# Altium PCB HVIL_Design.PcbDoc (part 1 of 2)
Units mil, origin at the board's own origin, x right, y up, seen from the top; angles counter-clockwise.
Board outline 4950 x 3450 mil, 2 copper layers (Top Layer, Bottom Layer), stack 62 mil thick; 93 components, 48 nets, 203 pads, 53 vias.
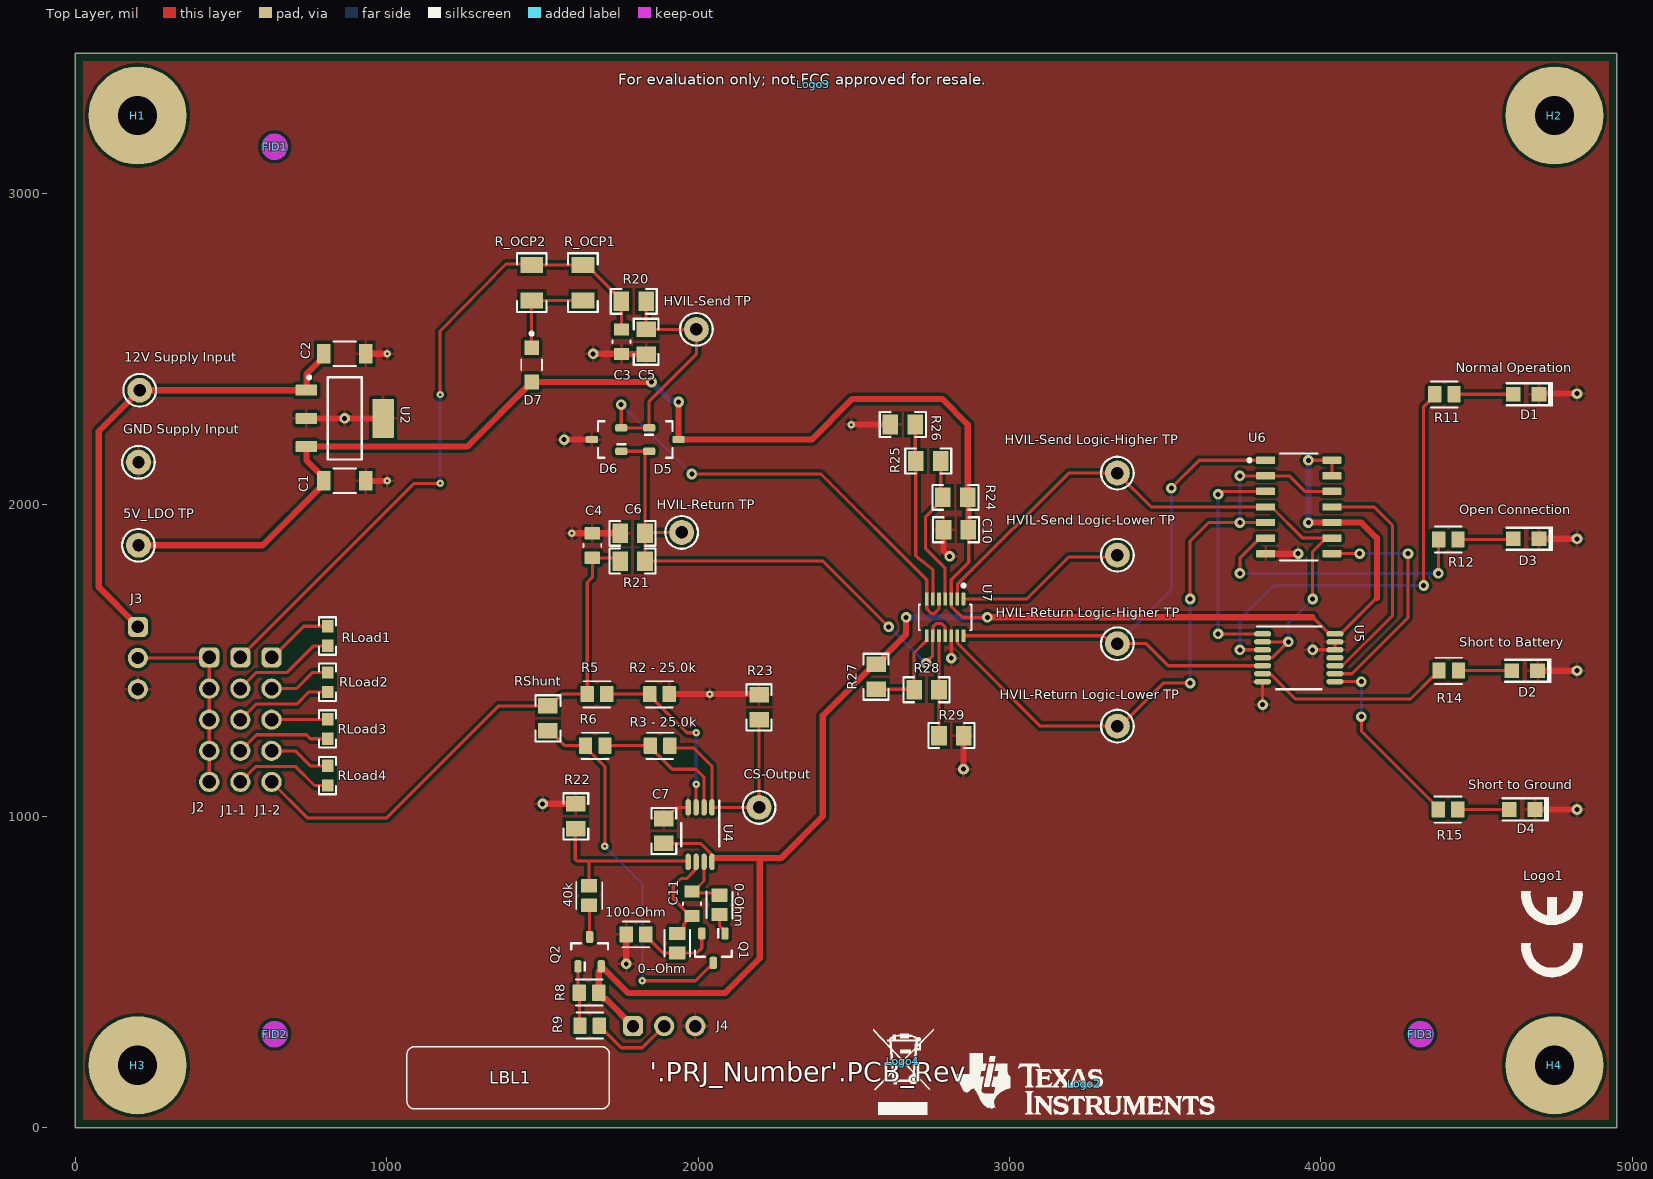
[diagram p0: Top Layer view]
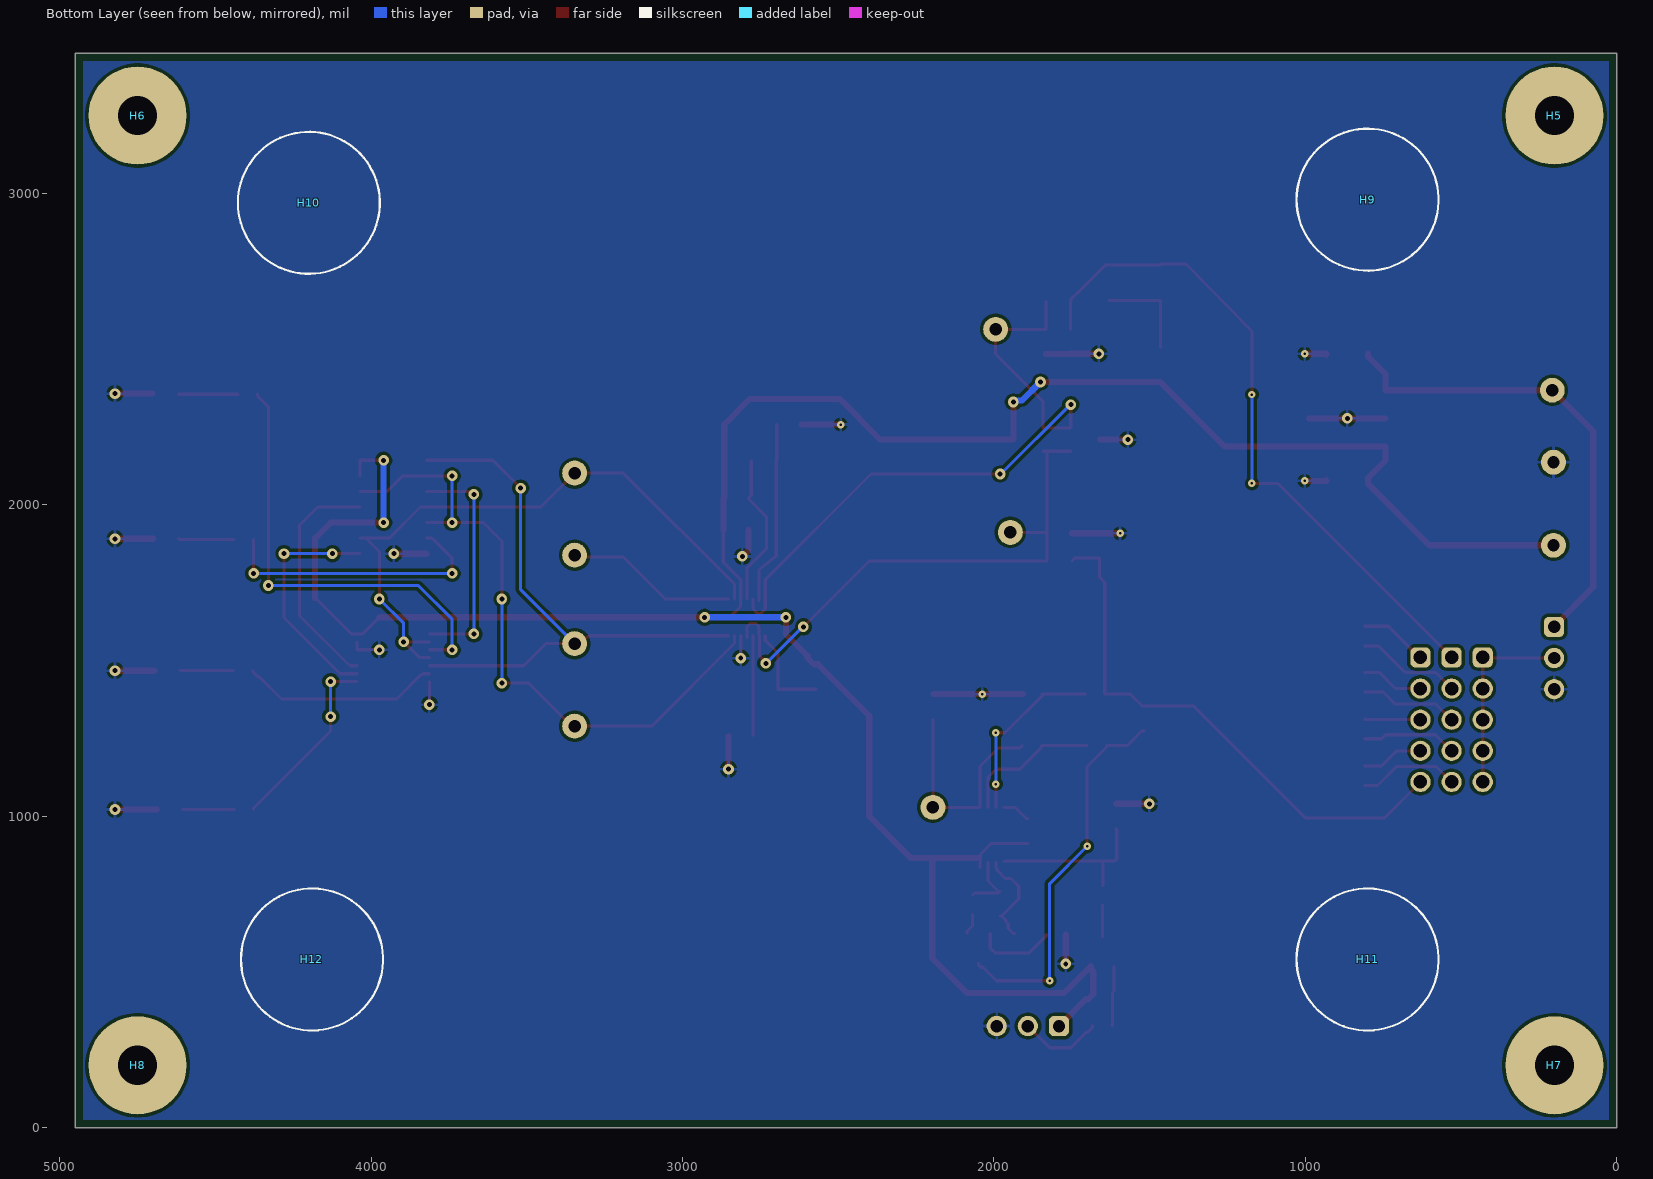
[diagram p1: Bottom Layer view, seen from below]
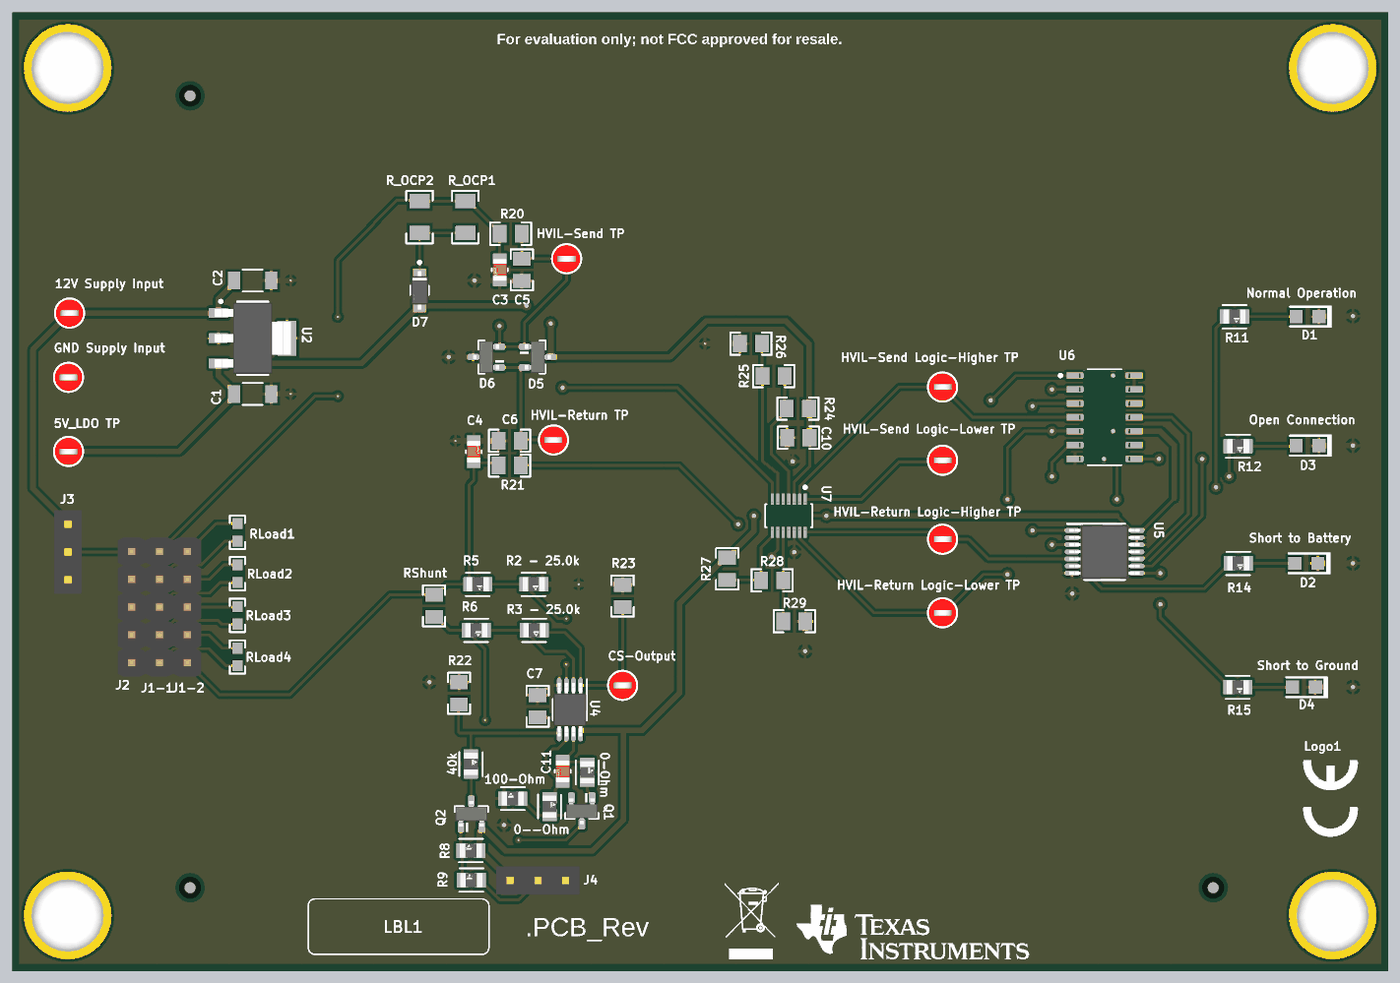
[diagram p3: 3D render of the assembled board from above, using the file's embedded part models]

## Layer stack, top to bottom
Top Solder: solder mask 0.4, Solder Resist, Dk 3.5
Top Layer: signal copper 1.4
Dielectric1: core 59.2, FR-4 High Tg, Dk 4.8
Bottom Layer: signal copper 1.4
Bottom Solder: solder mask 0.4, Solder Resist, Dk 3.5

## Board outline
0,0 4950,0 4950,3450 0,3450

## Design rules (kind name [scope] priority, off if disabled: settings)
AcuteAngle [All] p1: minimum=4.50000000000000E+0001 checktracksonly=FALSE
AssemblyTestPointUsage [All] p1: valid=2
BoardOutlineClearance BoardOutlineClearance_MountingHoles [OnCopper and InComponentClass('Mounting Holes')] p1: gap=39.37 ignorepadtopadclearanceinfootprint=FALSE
BoardOutlineClearance BoardOutlineClearance_Poly [OnCopper and IsPoly] p2: gap=25 ignorepadtopadclearanceinfootprint=FALSE
BoardOutlineClearance [OnCopper and Not InComponentClass('Logo') and not InComponentClass('FiducialMark') and not InRegion(1000,500,4000,800) and not InPoly] p3: gap=40 ignorepadtopadclearanceinfootprint=FALSE
Clearance Clearance_Keepouts [((IsTrack Or IsArc) And Not InPoly) And IsFree and IsKeepOut vs ((IsTrack Or IsArc) And Not InPoly) And IsFree and IsKeepOut] p1: gap=0 ignorepadtopadclearanceinfootprint=FALSE
Clearance Clearance_Poly [InPolygon] p2: gap=10 ignorepadtopadclearanceinfootprint=TRUE
Clearance Clearance_FiducialMark [IsKeepOut and InComponentClass('FiducialMark') vs IsPad and InComponentClass('FiducialMark')] p3: gap=0 ignorepadtopadclearanceinfootprint=FALSE
Clearance [All] p4: gap=7.87 ignorepadtopadclearanceinfootprint=TRUE
ComponentClearance ComponentClearance_MountingHoles_FiducialMarks [InComponentClass('Mounting Holes') vs InComponentClass('FiducialMark')] p1: gap=50 collisioncheckmode=3 verticalgap=10 showdistances=FALSE
ComponentClearance ComponentClearance_Shunt [InComponentClass('Header') vs InComponentClass('Shunt')] p2: gap=0 collisioncheckmode=3 verticalgap=0 showdistances=FALSE
ComponentClearance ComponentClearance_Logo [InComponentClass('Logo')] p3: gap=30 collisioncheckmode=3 verticalgap=10 showdistances=FALSE
ComponentClearance ComponentClearance_ScrewToNut [(HasFootprint('NY PMS 440 0025 PH')) vs (HasFootprint('Keystone_1902C'))] p4: gap=5 collisioncheckmode=3 verticalgap=10 showdistances=FALSE
ComponentClearance ComponentClearance_MountingHoles [InComponentClass('Mounting Holes')] p5: gap=100 collisioncheckmode=3 verticalgap=100000 showdistances=FALSE
ComponentClearance ComponentClearance_SmallPassives [HasFootprint('0201*') or HasFootprint('0402*') or HasFootprint('0508') or HasFootprint('0603*') or HasFootprint('0612') or HasFootprint('0805*') or HasFootprint('0815*') or HasFootprint('0830*') or HasFootprint('1206*') or HasFootprint('1210*') or HasFootprint('1808*') or HasFootprint('1812*') or HasFootprint('1825*') or HasFootprint('2010*') or HasFootprint('2220*') or HasFootprint('2225*') or HasFootprint('2512*') or HasFootprint('2728*') or HasFootprint('3518*') vs HasFootprint('0201*') or HasFootprint('0402*') or HasFootprint('0508') or HasFootprint('0603*') or HasFootprint('0612') or HasFootprint('0805*') or HasFootprint('0815*') or HasFootprint('0830*') or HasFootprint('1206*') or HasFootprint('1210*') or HasFootprint('1808*') or HasFootprint('1812*') or HasFootprint('1825*') or HasFootprint('2010*') or HasFootprint('2220*') or HasFootprint('2225*') or HasFootprint('2512*') or HasFootprint('2728*') or HasFootprint('3518*')] p6: gap=14.96 collisioncheckmode=3 verticalgap=10 showdistances=FALSE
ComponentClearance ComponentClearance_THtoSMT [IsThruComponent vs IsSMTComponent] p7: gap=30 collisioncheckmode=3 verticalgap=30 showdistances=FALSE
ComponentClearance ComponentClearance_THtoTH [IsThruComponent vs IsThruComponent] p8: gap=20 collisioncheckmode=3 verticalgap=30 showdistances=FALSE
ComponentClearance [All] p9: gap=20 collisioncheckmode=3 verticalgap=10 showdistances=FALSE
DiffPairsRouting [All] p1: maxlimit=100 minlimit=10 mostfreqgap=10 toplayer_minwidth=15 toplayer_maxwidth=15 toplayer_prefwidth=15 bottomlayer_minwidth=15 bottomlayer_maxwidth=15 bottomlayer_prefwidth=15 maxuncoupledlength=1000
FabricationTestPointUsage TestPointUsage [All] p1: valid=2 allowmultiple=FALSE
FabricationTestpoint Testpoint [All] p1: side=3 testpointundercomponent=TRUE minsize=40 maxsize=100 preferedsize=60 minholesize=0 maxholesize=40 preferedholesize=32 testpointgrid=1 allowsidetop=TRUE allowsidebottom=TRUE usegrid=TRUE gridtolerance=0.01
FanoutControl Fanout_LCC [IsLCC] p1: bgadir=Out bgaviamode=Centered fanoutstyle=Auto fanoutdirection=Alternating viagrid=1 // Fanout_LCC (Default Rule)
FanoutControl Fanout_BGA [IsBGA] p2: bgadir=Out bgaviamode=Centered fanoutstyle=Auto fanoutdirection=Alternating viagrid=1 // Fanout_BGA (Default Rule)
FanoutControl Fanout_Default [All] p4: bgadir=Out bgaviamode=Centered fanoutstyle=Auto fanoutdirection=Alternating viagrid=1 // Fanout_Default (Default Rule)
FanoutControl Fanout_Small [(CompPinCount < 5)] p5: bgadir=Out bgaviamode=Centered fanoutstyle=Auto fanoutdirection=OutThenIn viagrid=1 // Fanout_Small (Default Rule)
HoleSize [All] p1: absolutevalues=TRUE maxlimit=251 minlimit=7.87 maxpercent=80.000 minpercent=20.000
MinimumAnnularRing MinimumAnnularRing_ThermalPadVias [IsVia and InAnyComponent] p1: minimumring=5.91
MinimumAnnularRing [All] p2: minimumring=7.87
MinimumSolderMaskSliver MinimumSolderMaskSliver_Logo [InComponentClass('Logo') vs InComponentClass('Logo')] p1: minsoldermaskwidth=0.7
MinimumSolderMaskSliver [All] p2: minsoldermaskwidth=3.94
PlaneConnect [All] p1: planeconnectstyle=Relief reliefexpansion=10 reliefentries=4 reliefconductorwidth=10 reliefairgap=10
PolygonConnect [All] p1: connectstyle=Relief reliefconductorwidth=10 reliefentries=4 polygonreliefangle="90 Angle" airgapwidth=10
RoutingVias ThermalPadVias [IsVia and InAnyComponent] p1: holewidth=7.87 width=19.68 viastyle="Through Hole" minholewidth=7.87 minwidth=19.68 maxholewidth=12.99 maxwidth=23.62
RoutingVias [All] p2: holewidth=16 width=34 viastyle="Through Hole" minholewidth=7.87 minwidth=24 maxholewidth=40 maxwidth=65
SilkToBoardRegionClearance [Not ((IsComment or IsDesignator) And (Hide <> 'False')) and not InRegion(1000,500,4000,800)] p1:
SilkToSilkClearance SilkToSilkClearance_Pb-FreeLogo [(HasFootprint('Pb-Free_Overlay_Medium') OR HasFootprint('Pb-Free_Overlay_Small')) vs (HasFootprint('Pb-Free_Overlay_Medium') OR HasFootprint('Pb-Free_Overlay_Small'))] p1: silktosilkclearance=0
SilkToSilkClearance [All] p2: silktosilkclearance=3.94
SilkToSolderMaskClearance SilkToComponentPadClearance [(IsPad or IsFill or IsRegion) and InAnycomponent] p1: minsilkscreentomaskgap=5 clearancetoexposedcopper=TRUE
SilkToSolderMaskClearance "Silk to Solder Mask Opening" [All] p2: minsilkscreentomaskgap=3.94 clearancetoexposedcopper=FALSE
SolderMaskExpansion [All] p1: expansion=1.97 istentingtop=FALSE
UnRoutedNet [All] p1: checkbadconnections=TRUE
Width [All] p1: maxlimit=100 minlimit=6 preferedwidth=10 checkconnectedcopper=TRUE
14 further rules are at their usual default settings.

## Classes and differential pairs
component class HVIL_Design_BlankSheet: 0--Ohm 0-Ohm "5V_LDO TP" "12V Supply Input" 40k 100-Ohm C1 C2 C3 C4 C5 C6 C7 C10 C11 CS-Output D1 D2 D3 D4 D5 D6 D7 "GND Supply Input" "HVIL-Return Logic-Higher TP" "HVIL-Return Logic-Lower TP" "HVIL-Return TP" "HVIL-Send Logic-Higher TP" "HVIL-Send Logic-Lower TP" "HVIL-Send TP" J1-1 J1-2 J2 J3 J4 Q1 Q2 "R2 - 25.0k" "R3 - 25.0k" R5 R6 R8 R9 R11 R12 R14 R15 R20 R21 R22 R23 R24 R25 R26 R27 R28 R29 R_OCP1 R_OCP2 RLoad1 RLoad2 RLoad3 RLoad4 RShunt U2 U4 U5 U6 U7
component class Header: J1-1 J1-2 J2 J3 J4
component class Label: LBL1
component class AssemblyNote: ZZ1 ZZ2 ZZ3 ZZ4
component class FiducialMark: FID1 FID2 FID3
component class HVIL_Design_Hardware: FID1 FID2 FID3 H1 H2 H3 H4 H5 H6 H7 H8 H9 H10 H11 H12 LBL1 Logo1 Logo2 Logo3 Logo4 ZZ1 ZZ2 ZZ3 ZZ4
component class Logo: Logo2
component class "Mounting Holes": H1 H2 H3 H4

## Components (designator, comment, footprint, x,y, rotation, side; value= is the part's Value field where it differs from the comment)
0--Ohm "PCAN0805E1000BST5" FP-PCAN0805E1000BST5_0805-MFG 1932.95,592.26 r90 top value=100
0-Ohm "PCAN0805E1000BST5" FP-PCAN0805E1000BST5_0805-MFG 2068.86,715.25 r90 top value=100
"5V_LDO TP" "5000" Keystone5000 202.76,1870.08 r90 top
"12V Supply Input" "5000" Keystone5000 206.69,2368.11 r90 top
40k "PCAN0805E1001BST5" FP-PCAN0805E1001BST5_0805-MFG 1649.83,745.25 r90 top
100-Ohm "PCAN0805E1000BST5" FP-PCAN0805E1000BST5_0805-MFG 1800.52,620.53 r180 top value=100
C1 "CL31B106KBHNNNE" 1206_180 865.16,2076.77 r180 top value=10uF
C2 "CL31B106KBHNNNE" 1206_180 865.16,2485.06 r180 top value=10uF
C3 "08055F103K4T2A" FP-08055F103K4T2A_0805-MFG 1753.94,2523.62 r270 top
C4 "08055F103K4T2A" FP-08055F103K4T2A_0805-MFG 1660.43,1869.09 r90 top
C5 "GCM21BR71H104KA37K" 0805_HV 1833.31,2523.62 r90 top value=0.1uF
C6 "GCM21BR71H104KA37K" 0805_HV 1789.37,1908.39 r0 top value=0.1uF
C7 "GCM21BR71H104KA37K" 0805_HV 1890,952.72 r90 top value=0.1uF
C10 "GCM21BR71H104KA37K" 0805_HV 2828.03,1920 r180 top value=0.1uF
C11 "08055F103K4T2A" FP-08055F103K4T2A_0805-MFG 1980.28,718.88 r270 top
CS-Output "5000" Keystone5000 2195.87,1028.36 r90 top
D1 "LTST-C170KGKT" LTST-C170KGKT_Green 4659.45,2355.31 r0 top value=Green
D2 "LTST-C170KRKT" LED_LTST-C170_Red 4654.73,1467.52 r0 top value=Red
D3 "LTST-C170KSKT" LED_LTST-C170 4659.45,1891.05 r0 top value=Yellow
D4 "LTST-C170KRKT" LED_LTST-C170_Red 4646.38,1021.65 r0 top value=Red
D5 "BAT54C-7-F" SOT-23 1890.16,2209.66 r0 top value=30V
D6 "BAT54A-7-F" SOT-23 1706.06,2209.66 r180 top value=30V
D7 "PMEG4010EH,115" FP-PMEG4010EH_115_SOD123F-MFG 1465.55,2449.62 r270 top
FID1 "Fiducial" Fiducial10-20 640,3150 r0 top
FID2 "Fiducial" Fiducial10-20 640,300 r0 top
FID3 "Fiducial" Fiducial10-20 4320,300 r0 top
"GND Supply Input" "5000" Keystone5000 202.76,2136.81 r90 top
H1 "NY PMS 440 0025 PH" "NY PMS 440 0025 PH" 200,3250 r0 top locked
H2 "NY PMS 440 0025 PH" "NY PMS 440 0025 PH" 4750,3250 r0 top locked
H3 "NY PMS 440 0025 PH" "NY PMS 440 0025 PH" 200,200 r0 top locked
H4 "NY PMS 440 0025 PH" "NY PMS 440 0025 PH" 4750,200 r0 top locked
H5 "1902C" Keystone_1902C 200,3250 r180 bottom locked
H6 "1902C" Keystone_1902C 4750,3250 r180 bottom locked
H7 "1902C" Keystone_1902C 200,200 r180 bottom locked
H8 "1902C" Keystone_1902C 4750,200 r180 bottom locked
H9 "SJ-5303 (CLEAR)" Bumpon_SJ5003Transparent 800,2980 r180 bottom
H10 "SJ-5303 (CLEAR)" Bumpon_SJ5003Transparent 4200,2970 r180 bottom
H11 "SJ-5303 (CLEAR)" Bumpon_SJ5003Transparent 800,540 r180 bottom
H12 "SJ-5303 (CLEAR)" Bumpon_SJ5003Transparent 4190,540 r180 bottom
"HVIL-Return Logic-Higher TP" "5000" Keystone5000 3346.46,1554.13 r90 top
"HVIL-Return Logic-Lower TP" "5000" Keystone5000 3346.46,1289.37 r90 top
"HVIL-Return TP" "5000" Keystone5000 1947.12,1911.42 r90 top
"HVIL-Send Logic-Higher TP" "5000" Keystone5000 3346.46,2101.97 r90 top
"HVIL-Send Logic-Lower TP" "5000" Keystone5000 3346.46,1838.4 r90 top
"HVIL-Send TP" "5000" Keystone5000 1994.43,2563.62 r90 top
J1-1 "61300511121" Wurth_61300511121 530,1310 r270 top
J1-2 "61300511121" Wurth_61300511121 630,1310 r270 top
J2 "61300511121" Wurth_61300511121 430,1310 r270 top
J3 "TSW-103-07-G-S" TSW-103-07-G-S 200.79,1508.06 r270 top
J4 "TSW-103-07-G-S" TSW-103-07-G-S 1890.98,326.18 r0 top
LBL1 "THT-14-423-10" Label_650x200 1390,160 r0 top
Logo1 "CE Mark" CE_Mark_5mm 4742.13,621.06 r90 top
Logo2 "Texas Instruments" TI_Stacked_Overlay_Small 3240,140 r0 top
Logo3 "FCC disclaimer" FCC_disclaimer 2370,3350 r0 top
Logo4 "WEEE logo" WEEE_Minimum 2657.48,213.79 r0 top
Q1 "MMBTA05LT1G" SOT-23 2049.18,576.27 r270 top value="60 V"
Q2 "BC807-40LT1G" SOT-23 1651.57,565.09 r90 top value="45 V"
"R2 - 25.0k" "PCAN0805E1001BST5" FP-PCAN0805E1001BST5_0805-MFG 1875.98,1392.13 r0 top
"R3 - 25.0k" "PCAN0805E1001BST5" FP-PCAN0805E1001BST5_0805-MFG 1877.95,1226.55 r0 top
R5 "PCAN0805E1001BST5" FP-PCAN0805E1001BST5_0805-MFG 1675.2,1392.13 r0 top
R6 "PCAN0805E1001BST5" FP-PCAN0805E1001BST5_0805-MFG 1669.7,1226.55 r0 top
R8 "PCAN0805E1001BST5" FP-PCAN0805E1001BST5_0805-MFG 1649.83,433.2 r180 top
R9 "PCAN0805E1001BST5" FP-PCAN0805E1001BST5_0805-MFG 1651.57,327.13 r180 top
R11 "PCAN0805E1001BST5" FP-PCAN0805E1001BST5_0805-MFG 4396.79,2355.31 r0 top
R12 "PCAN0805E1001BST5" FP-PCAN0805E1001BST5_0805-MFG 4409.56,1889.09 r0 top
R14 "PCAN0805E1001BST5" FP-PCAN0805E1001BST5_0805-MFG 4410.43,1467.52 r0 top
R15 "PCAN0805E1001BST5" FP-PCAN0805E1001BST5_0805-MFG 4408.54,1021.65 r0 top
R20 "MCU0805MD1002BP100" 0805_HV 1793.31,2653.54 r0 top value=10.0k
R21 "MCU0805MD1002BP100" 0805_HV 1789.37,1819.43 r0 top value=10.0k
R22 "MCU0805MD1002BP100" 0805_HV 1607.29,999.72 r90 top value=10.0k
R23 "MCU0805MD1002BP100" 0805_HV 2195.87,1349.65 r90 top value=10.0k
R24 "MCU0805MD1002BP100" 0805_HV 2826.32,2024.2 r180 top value=10.0k
R25 "MCU0805MD1002BP100" 0805_HV 2739.17,2140.76 r180 top value=10.0k
R26 "MCU0805MD1002BP100" 0805_HV 2657.48,2257.87 r180 top value=10.0k
R27 "MCU0805MD1002BP100" 0805_HV 2571.65,1447.78 r270 top value=10.0k
R28 "MCU0805MD1002BP100" 0805_HV 2733.62,1406.14 r0 top value=10.0k
R29 "MCU0805MD1002BP100" 0805_HV 2813.62,1258.91 r0 top value=10.0k
R_OCP1 "CRCW1206220RJNEA" 1206 1630.31,2713.58 r90 top value=220
R_OCP2 "CRCW1206220RJNEA" 1206 1465.55,2713.58 r90 top value=220
RLoad1 "FC0603E50R0BTBST1" 0603 810.04,1578.74 r270 top value=50
RLoad2 "FC0603E50R0BTBST1" 0603 810.04,1430.32 r270 top value=50
RLoad3 "FC0603E50R0BTBST1" 0603 810.04,1280.31 r270 top value=50
RLoad4 "FC0603E50R0BTBST1" 0603 810.04,1130.32 r270 top value=50
RShunt "PATT0805E10R0BGT1" 0805_HV 1517.72,1314.37 r270 top value=10.0
U2 "TPS7B6950QDCYRQ1" DCY0004A_N 865.16,2277.56 r0 top
U4 "TLV9002QDRQ1" DGK0008A_N 2006.23,940.76 r270 top
U5 "SN74HCS08QPWRQ1" PW0014A_N 3929.13,1508.86 r0 top
U6 "SN74HCS86DR" D0014A-MFG 3929.13,1993.11 r0 top
U7 "TLV9034QDYYRQ1" DYY0014A-MFG 2793.31,1638.63 r270 top
ZZ1 "This Assembly Note is for PCB labels only" AssemblyNoteLabel 185,3938 r0 top
ZZ2 "These assemblies are ESD sensitive, ESD precautions shall be observed." AssemblyNote 185,3829.11 r0 top
ZZ3 "These assemblies must be clean and free from flux and all contaminants. Use of no clean flux is not acceptable." AssemblyNote 185,3740.56 r0 top
ZZ4 "These assemblies must comply with workmanship standards IPC-A-610 Class 2, unless otherwise specified." AssemblyNote 185,3652 r0 top

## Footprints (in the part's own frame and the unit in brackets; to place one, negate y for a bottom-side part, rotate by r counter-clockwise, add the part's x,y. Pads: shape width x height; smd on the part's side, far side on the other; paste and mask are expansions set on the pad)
0603 [mm] "0603 from SM-752 data"
  rect 1x0.95 smd: 1(-0.8,0) 2(0.8,0)
  silkscreen extent -1.52,-0.69 1.52,0.69, body extent -0.87,-0.47 0.87,0.47, height 1
0805_HV [mil] "0805 with 30mil clearance between pads"
  rect 50x63 smd: 1(-40,0) 2(40,0)
  silkscreen extent -74,-40 74,40, body extent -43,-29 43,29, height 57
1206 [mm] "1206 from SM-752 data"
  rect 1.3x1.85 smd: 1(-1.45,0) 2(1.45,0)
  silkscreen extent -2.4,-1.21 2.4,1.21, body extent -1.7,-0.9 1.7,0.9, height 1.35
1206_180 [mm] "1206_180"
  rect 1.1x1.6 smd: 1(-1.7,0) 2(1.7,0)
  silkscreen extent -0.9,-1 0.9,1, body extent -1.75,-0.95 1.75,0.95, height 1.8
AssemblyNote [mil] "Assembly Note"
AssemblyNoteLabel [mil] "Assembly Note for PCB Labels"
Bumpon_SJ5003Transparent [mil] "3M Hemispherical Bumpon transparent"
  round 1 on Mech4: 0(0,0)
  silkscreen extent -228,-228 228,228, body extent -218,-218 219,218, height 197
CE_Mark_5mm [mil] "Minimum text height for CE Mark"
  silkscreen extent -138,-98 138,98
D0014A-MFG [mm]
  rrect17% 1.55x0.6 smd paste-1000 mask+0: 1(-2.7,3.81) 2(-2.7,2.54) 3(-2.7,1.27) 4(-2.7,0) 5(-2.7,-1.27) 6(-2.7,-2.54) 7(-2.7,-3.81) 8(2.7,-3.81) 9(2.7,-2.54) 10(2.7,-1.27) 11(2.7,0) 12(2.7,1.27) 13(2.7,2.54) 14(2.7,3.81)
  silkscreen extent -4.15,-4.38 1.55,4.38, body extent -3.57,-4.62 3.57,4.62, height 0.25
DCY0004A_N [mm] "SOT223/SC73, 4-Leads, Body 6.5x3.5mm, Pitch 2.3mm, Lead Span 7mm, IPC Medium Density"
  rrect11% 1.75x0.9 smd: 1(-3.125,2.3) 2(-3.125,0) 3(-3.125,-2.3)
  rrect6% 1.75x3.2 smd: 4(3.125,0)
  silkscreen extent -3.02,-3.35 1.4,3.47, body extent -3.48,-3.25 3.48,3.25, height 1.68
DGK0008A_N [mm] "TSOP, 8-Leads, Body 3x3mm, Pitch 0.65mm, IPC Medium Density"
  oval 1.35x0.45 smd: 1(-2.225,0.975) 2(-2.225,0.325) 3(-2.225,-0.325) 4(-2.225,-0.975) 5(2.225,-0.975) 6(2.225,-0.325) 7(2.225,0.325) 8(2.225,0.975)
  silkscreen extent -2.75,-1.55 0.95,1.55, body extent -2.45,-1.5 2.45,1.5, height 0.96
DYY0014A-MFG [mm]
  rrect33% 1.05x0.3 smd paste+0 mask+0: 1(-1.5,1.5) 2(-1.5,1) 3(-1.5,0.5) 4(-1.5,0) 5(-1.5,-0.5) 6(-1.5,-1) 7(-1.5,-1.5) 8(1.5,-1.5) 9(1.5,-1) 10(1.5,-0.5) 11(1.5,0) 12(1.5,0.5) 13(1.5,1) 14(1.5,1.5)
  silkscreen extent -2.72,-2.15 1.05,2.15, body extent -2.12,-2.4 2.12,2.4, height 0.25
FCC_disclaimer [mil]
Fiducial10-20 [mm]
  round 1 smd mask+0.5: 1(0,0)
  Top Layer keep-out circle w1.178: c0,0 r0.5
FP-08055F103K4T2A_0805-MFG [mm]
  rrect10% 1x1.25 smd paste+0 mask+0: 1(-1,0) 2(1,0)
  silkscreen extent -0.13,-0.72 0.13,0.72, body extent -1.6,-0.82 1.6,0.82, height 0.25
FP-PCAN0805E1000BST5_0805-MFG [mil]
  rrect9% 42.5x52 smd paste+0 mask+0: 1(-31.25,0) 2(31.25,0)
  silkscreen extent -44,-41 43,41, body extent -56,-31 56,31, height 10
FP-PCAN0805E1001BST5_0805-MFG [mil]
  rrect9% 42.5x52 smd paste+0 mask+0: 1(-31.25,0) 2(31.25,0)
  silkscreen extent -44,-42 43,41, body extent -56,-31 56,31, height 10
FP-PMEG4010EH_115_SOD123F-MFG [mm]
  rrect8% 1.2x1.2 smd paste-1000 mask+0: 1(-1.4,0) 2(1.4,0)
  silkscreen extent -2.67,-0.85 0.43,0.85, body extent -2.2,-1.05 2.2,1.05, height 0.25
Keystone5000 [mil] "For Keystone 500x miniature loop terminals"
  round 80 hole 40: 1(0,0)
  silkscreen extent -52,-52 52,52, body extent -49,-49 49,49, height 182
Keystone_1902C [mil] "Hex Standoff, 4-40 threaded, nylon"
  round 1 on Mech4: 0(0,0)
  body extent -145,-126 146,126, height 501
Label_650x200 [mil] "Thermal Transfer Label"
  round 1 on Mech13: 0(0,0)
  silkscreen extent -325,-100 325,100, body extent -325,-100 325,100, height 1
LED_LTST-C170 [mm] "LITE-ON"
  rect 1.2x1.2 smd: 1(-1.05,0) 2(1.05,0)
  silkscreen extent -1.6,-1 2.2,1, body extent -1.05,-0.67 1.05,0.67, height 1.1
LED_LTST-C170_Red [mm] "LITE-ON"
  rect 1.2x1.2 smd: 1(-1.05,0) 2(1.05,0)
  silkscreen extent -1.6,-1 2.2,1, body extent -1.05,-0.67 1.05,0.67, height 1.1
LTST-C170KGKT_Green [mm] "LITE-ON"
  rect 1.2x1.2 smd: 1(-1.05,0) 2(1.05,0)
  silkscreen extent -1.6,-1 2.2,1, body extent -1.05,-0.67 1.05,0.67, height 1.1
"NY PMS 440 0025 PH" [mm] "4-40 nylon screw and mounting hole"
  round 8 hole 3.2: 1(0,0)
  body extent -3.3,-3.3 3.3,3.3, height 2.69
PW0014A_N [mm] "TSOP, 14-Leads, Body 5x4.4mm, Pitch 0.65mm, IPC Medium Density"
  oval 1.4x0.45 smd: 1(-2.95,1.95) 2(-2.95,1.3) 3(-2.95,0.65) 4(-2.95,0) 5(-2.95,-0.65) 6(-2.95,-1.3) 7(-2.95,-1.95) 8(2.95,-1.95) 9(2.95,-1.3) 10(2.95,-0.65) 11(2.95,0) 12(2.95,0.65) 13(2.95,1.3) 14(2.95,1.95)
  silkscreen extent -3.4,-2.55 1.85,2.55, body extent -3.21,-2.5 3.21,2.5, height 1
SOT-23 [mm] "SOT23, 3-Leads, Body 2.9x1.3mm, Pitch 0.95mm, Lead Span 2.5mm, IPC Medium Density"
  rrect50% 1x0.6 smd: 1(-1.2,0.95) 2(-1.2,-0.95) 3(1.2,0)
  silkscreen extent -1.62,-1.5 0.7,1.5, body extent -1.16,-1.45 1.21,1.45, height 1
TI_Stacked_Overlay_Small [mil]
  silkscreen extent -418,-98 418,98
TSW-103-07-G-S [mm] "Samtec 100mil, 1x3, 230 mil above insulator"
  rrect50% 1.65x1.65 hole 1.016: 1(-2.54,0)
  round 1.65 hole 1.016: 2(0,0) 3(2.54,0)
  body extent -3.81,-1.27 3.81,1.27, height 8.38
WEEE_Minimum [mil] "WEEElie bin"
  silkscreen extent -95,-172 99,104
Wurth_61300511121 [mm] "Header, 2.54mm, 5x1, TH"
  rrect50% 1.65x1.65 hole 1.1: 1(-5.08,0)
  round 1.65 hole 1.1: 2(-2.54,0) 3(0,0) 4(2.54,0) 5(5.08,0)
  body extent -6.35,-1.27 6.35,1.27, height 8.54

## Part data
0--Ohm 0-Ohm 100-Ohm: library part CMP-0091946-1, "100 Ohms ±0.1% 1W Chip Resistor 0805 (2012 Metric) Flame Proof, Moisture Resistant, Safety Thin Film", Digikey Part Number=764-1239-1-ND, Manufacturer=Vishay, Mouser Part Number=71-PCAN0805E1000BST5, Operating Temperature Range="-55°C to +155°C", Power_W=1W, TempCo=25ppm/°C, Tolerance_%=0.1%
"5V_LDO TP" "12V Supply Input" CS-Output "GND Supply Input" "HVIL-Return Logic-Higher TP" "HVIL-Return Logic-Lower TP" "HVIL-Return TP" "HVIL-Send Logic-Higher TP" "HVIL-Send Logic-Lower TP" "HVIL-Send TP": library part CMP-0055137-2, "Test Point, Miniature, Red, TH", Color=Red, Manufacturer="Keystone Electronics", Supplier Part Number 1=36-5000-ND
40k "R2 - 25.0k" R5 R6 R8 R9 R11 R12 R14 R15: library part CMP-0089213-1, "1 kOhms ±0.1% 1W Chip Resistor 0805 (2012 Metric) Flame Proof, Moisture Resistant, Safety Thin Film", Digikey Part Number=764-1240-1-ND, Manufacturer=Vishay, Mouser Part Number=71-PCAN0805E1001BST5, Operating Temperature Range="-55°C to +155°C", Power_W=1W, TempCo=25ppm/°C, Tolerance_%=0.1%
C1 C2: library part CMP-0008802-2, "CAP, CERM, 10 uF, 50 V, +/- 10%, X7R, 1206", Cap_Case=1206, Manufacturer=Samsung, Supplier Part Number 1=1276-6767-1-ND, TempCo=X7R, Tolerance_%=10%, Value1=Unknown, Value2=50V, ValueDisplayed=10uF
C3 C4: library part CMP-0089555-2, "CAP, CERM, 10000 pF, 50 V,+/- 10%, X8R, AEC-Q200 Grade 0, 0805", Digikey Part Number=478-3609-1-ND, Manufacturer=AVX, Mouser Part Number=581-08055F103K4, Operating Temperature Range="-55°C to +150°C", TempCo=15%, Temperature Characteristic=X8R, Tolerance_%=10%, ValueDisplayed=0.01uF
C5 C6 C7 C10: library part CMP-0008021-2, "CAP, CERM, 0.1 uF, 50 V, +/- 10%, X7R, AEC-Q200 Grade 1, 0805", Cap_Case=0805, Manufacturer=MuRata, Supplier Part Number 1=490-8049-1-ND, TempCo=X7R, Tolerance_%=10%, Value1=Unknown, Value2=50V, ValueDisplayed=0.1uF
C11: library part CMP-0089555-2, "CAP, CERM, 10000 pF, 50 V,+/- 10%, X8R, AEC-Q200 Grade 0, 0805", Digikey Part Number=478-3609-1-ND, Manufacturer=AVX, Mouser Part Number=581-08055F103K4, Operating Temperature Range="-55°C to +150°C", TempCo=15%, Temperature Characteristic=X8R, Tolerance_%=10%, ValueDisplayed=0uF
D1: library part CMP-0002888-2, "LED, Green, SMD", Color=Green, Manufacturer=Lite-On, Value1=W, Value2=2V
D2 D4: library part CMP-0002829-3, "LED, Red, SMD", Color=red, Manufacturer=Lite-On, Value1=W, Value2=2V
D3: library part CMP-0002862-2, "LED, Yellow , SMD", Color=yellow, Manufacturer=Lite-On, Value1=W, Value2=2V
D5: library part CMP-0028453-2, "Diode, Schottky, 30 V, 0.2 A, SOT-23", Manufacturer="Diodes Inc.", Value1=0.2A, Value2=0.65V
D6: library part CMP-0028452-2, "Diode, Schottky, 30 V, 0.2 A, SOT-23", Manufacturer="Diodes Inc.", Value1=0.2A, Value2=0.65V
D7: library part CMP-0091342-2, "Diode Schottky 40V 1A (DC) Surface Mount SOD-123F", Digikey Part Number=1727-3880-1-ND, Forward Current=1A, Manufacturer=Nexperia, Max Surge Forward Current=9A, Mouser Part Number=771-PMEG4010EH-T/R, Operating Temperature Range="to +150°C", Peak Reverse Current=30uA, ValueDisplayed=43pF
FID1 FID2 FID3: library part CMP-0077181-1, "Fiducial mark.  There is nothing to buy or mount.", Manufacturer=N/A
H1 H2 H3 H4: library part CMP-0003617-1, "Machine Screw, Round, #4-40 x 1/4, Nylon, Philips panhead", Manufacturer="B&F Fastener Supply", Supplier Part Number 1=H542-ND
H5 H6 H7 H8: library part CMP-0003610-1, "Standoff, Hex, 0.5\"L #4-40 Nylon", Manufacturer=Keystone, Supplier Part Number 1=36-1902C-ND
H9 H10 H11 H12: library part CMP-0003620-1, "Bumpon, Hemisphere, 0.44 X 0.20, Clear", Manufacturer=3M, Supplier Part Number 1=SJ5303-7-ND
J1-1 J1-2 J2: library part CMP-0084909-1, "Header, 2.54mm, 5x1, Gold, TH", Color=Black, Current_A=3A, Manufacturer="Wurth Elektronik", Voltage_V=250V
J3 J4: library part CMP-0075407-2, "Header, 100mil, 3x1, Gold, TH", Color=Black, Current_A=6.3A, Manufacturer=Samtec, Supplier Part Number 1=SAM1029-03-ND, Voltage_V=550V
LBL1: library part CMP-0003625-1, "Thermal Transfer Printable Labels, 0.650\" W x 0.200\" H - 10,000 per roll", Manufacturer=Brady, Supplier Part Number 1=97C5133
Logo1: library part CMP-0074844-1
Logo2: library part CMP-0074838-1, "Texas Instrument Corporate Signature"
Logo3: library part CMP-0074847-1, "FCC_disclaimer"
Logo4: library part CMP-0074769-1
Q1: library part CMP-0000488-2, "Transistor, NPN, 60 V, 0.5 A, AEC-Q101, SOT-23", Manufacturer="ON Semiconductor", Supplier Part Number 1=MMBTA05LT1GOSCT-ND, Value1="0.5 A"
Q2: library part CMP-0000367-2, "Transistor, PNP, 45 V, 0.5 A, AEC-Q101, SOT-23", Manufacturer="ON Semiconductor", Supplier Part Number 1=BC807-40LT1GOSCT-ND, Value1="0.5 A", Value2=600
"R3 - 25.0k": library part CMP-0089213-1, "25 kOhms ±0.1% 1W Chip Resistor 0805 (2012 Metric) Flame Proof, Moisture Resistant, Safety Thin Film", Digikey Part Number=764-1240-1-ND, Manufacturer=Vishay, Mouser Part Number=71-PCAN0805E1001BST5, Operating Temperature Range="-55°C to +155°C", Power_W=1W, TempCo=25ppm/°C, Tolerance_%=0.1%
R20 R21 R22 R23 R24 R25 R26 R27 R28 R29: library part CMP-0018838-2, "RES, 10.0 k, 0.1%, 0.2 W, AEC-Q200 Grade 0, 0805", Manufacturer=Vishay/Beyschlag, Power_W=200mW, Supplier Part Number 1=MCU0805-10.0K-MBCT-ND, TempCo="25 ppm/C", Tolerance_%=0.1%, Value2=0.2W, Value_Code=10k0, ValueDisplayed=10.0k
R_OCP1 R_OCP2: library part CMP-0018629-3, "RES, 220, 5%, 0.25 W, AEC-Q200 Grade 0, 1206", Manufacturer=Vishay-Dale, Power_W=250mW, Supplier Part Number 1=541-220ECT-ND, TempCo="200 ppm/C", Tolerance_%=5%, Value2=0.25W, Value_Code=220R, ValueDisplayed=220
RLoad1 RLoad2 RLoad3 RLoad4: library part CMP-0023387-3, "RES, 50, 0.1%, 0.125 W, 0603", Manufacturer="Vishay Thin Film", Power_W=125mW, Supplier Part Number 1=FC0603-50BFCT-ND, TempCo="25 ppm/C", Tolerance_%=0.1%, Value2=0.125W, Value_Code=50R0, ValueDisplayed=50
RShunt: library part CMP-0018841-2, "RES, 10.0, 0.1%, 0.2 W, AEC-Q200 Grade 0, 0805", Manufacturer="Vishay Thin Film", Power_W=200mW, TempCo="25 ppm/C", Tolerance_%=0.1%, Value2=0.2W, Value_Code=10R0, ValueDisplayed=10.0
U2: library part CMP-0077337-1, "Automotive High-Voltage Ultra-Low IQ Low-Dropout Regulator/Fixed 5-V Output Voltage, DCY0004A (SOT-223-4)", Alternate Manufacturer="Texas Instruments"
U4: library part CMP-0084063-1, "10-MHz, Low-Noise, RRIO, CMOS Operational Amplifier for Cost-Sensitive Systems, DGK0008A (VSSOP-8)", Alternate Manufacturer="Texas Instruments", Alternate PartNumber=TLV9062IDGKT, Operating Temperature Range="-40 to 125 C", PartNumber=TLV9002QDGKRQ1, Rating=Catalog
U5: library part CMP-0860019-1, "QUADRUPLE 2-INPUT POSITIVE-AND GATE, PW0014A (TSSOP-14)", Alternate Manufacturer="Texas Instruments"
U6: library part CMP-0094930-1, "Quadruple 2-Input XOR Gates with Schmitt-Trigger Inputs", Digikey Part Number=296-SN74HCS86DRCT-ND, Manufacturer="Texas Instruments", Max Supply Voltage=6V, Min Supply Voltage=2V, Mouser Part Number=595-SN74HCS86DR, Nominal Supply Current=0.1uA, Operating Temperature Range="-40°C to +125°C", PartNumber=SN74HCS86QDRQ1
U7: library part CMP-0091442-1, "High-Precision Quad Comparator, Push-Pull output, Automotive, TSOT23-14", Input Bias Current=0.000005uA, Input Offset Voltage=0.3mV, Manufacturer="Texas Instruments", Max Supply Voltage=5.5V, Min Supply Voltage=1.65V, Nominal Supply Current=16uA, Operating Temperature Range="-40°C to +125°C", Output Current Per Channel=100mA, Voltage Gain=200V/mV
ZZ1: library part CMP-0003616-3
ZZ2: library part CMP-0077236-1
ZZ3: library part CMP-0077237-1
ZZ4: library part CMP-0077238-1

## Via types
v1: diameter 34, hole 16, Top Layer to Bottom Layer, tented both sides, 42 vias
v2: diameter 24, hole 8, Top Layer to Bottom Layer, tented both sides, 11 vias

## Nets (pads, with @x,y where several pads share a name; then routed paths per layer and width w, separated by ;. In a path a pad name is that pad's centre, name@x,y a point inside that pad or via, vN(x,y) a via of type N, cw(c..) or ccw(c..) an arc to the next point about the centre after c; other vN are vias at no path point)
5V_LDO: "5V_LDO TP.1" C1.2 C7.1 C10.1 D5.3 D7.2 J4.1 Q2.2 R8.1 R24.1 R27.1 U2.3 U4.8 U5.14 U6.10 U6.13 U6.14 U7.3 | length 8881.4
  Top Layer w10: C7.1@1890,912.72 2007.92,912.72 2043.14,877.5 U4.8@2043.14,870.92 ; U4.8@2044.61,835.44 U4.8@2044.61,853.16 2043.14,854.64 U4.8@2043.14,870.92 ; U4.8@2048.18,865.88 U4.8@2043.14,870.92 ; R24.1@2866.32,2024.2 R24.1@2868.03,2022.49 ; C10.1@2868.03,1920 2869.28,1918.76 2869.28,1815.76 2812.99,1759.48 U7.3@2812.99,1697.68 2813.9,1696.78 2813.9,1672.82 2848.09,1638.63 v1(2928.8,1638.63) ; v1(3960,2143.11) U6.14@4035.43,2143.11 U6.13@4035.43,2093.11 ; 3973.58,1638.63 4026.57,1585.63 U5.14@4045.28,1585.63 4063.98,1585.63 4180,1701.65
  Top Layer w20: 202.76,1870.08 601.38,1870.08 798.23,2066.93 C1.2@798.23,2076.77 798.23,2086.61 742.13,2142.72 U2.3@742.13,2187.01 1258.06,2187.01 D7.2@1465.55,2394.5 v1(1850.31,2394.5) ; Q2.2@1688.97,517.84 Q2.2@1688.97,509.97 ; J4.1@1790.98,326.18 1704.96,412.2 1697.33,412.2 1681.08,428.45 R8.1@1681.08,433.2 1681.08,501.59 1688.97,509.48 Q2.2@1688.97,509.97 ; v1(1937.4,2330.36) D5.3@1937.4,2209.66 2364.97,2209.66 2495.31,2340 2784.2,2340 2866.32,2257.87 R24.1@2866.32,2024.2 ; U4.8@2048.18,865.88 2198.35,865.88 ; v1(2668.13,1638.63) 2668.13,1584.25 2598.15,1514.28 2598.15,1507.78 2578.15,1487.78 R27.1@2571.65,1487.78 2565.15,1487.78 2400.49,1323.12 2400.49,999.72 2266.65,865.88 2198.35,865.88 ; C10.1@2868.03,1920 R24.1@2868.03,2022.49 ; v1(2928.8,1638.63) 3973.58,1638.63 ; v1(3960,1943.11) U6.10@4035.43,1943.11 4130,1943.11 4180,1893.11 4180,1701.65 ; Q2.2@1688.97,509.97 1690.78,508.16 1698.66,508.16 1774.49,432.33 2086.58,432.33 2198.35,544.1 2198.35,865.88
  Bottom Layer w20: v1(1850.31,2394.5) 1909.86,2334.95 1932.81,2334.95 v1(1937.4,2330.36) ; v1(2668.13,1638.63) v1(2928.8,1638.63) ; v1(3960,1943.11) v1(3960,2143.11)
12V_Input: "12V Supply Input.1" C2.2 J3.1 U2.1 | length 1540.3
  Top Layer w20: J3.1@200.79,1610.24 74.8,1736.22 74.8,2236.22 206.69,2368.11 U2.1@742.13,2368.11 742.13,2419.11 798.23,2475.21 C2.2@798.23,2485.06
"Disable Input": J4.2 R9.1 | length 269.2
  Top Layer w10: R9.1@1682.82,327.13 1682.82,322.38 1699.07,306.13 1703.82,306.13 1753.65,256.3 1821.1,256.3 J4.2@1890.98,326.18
